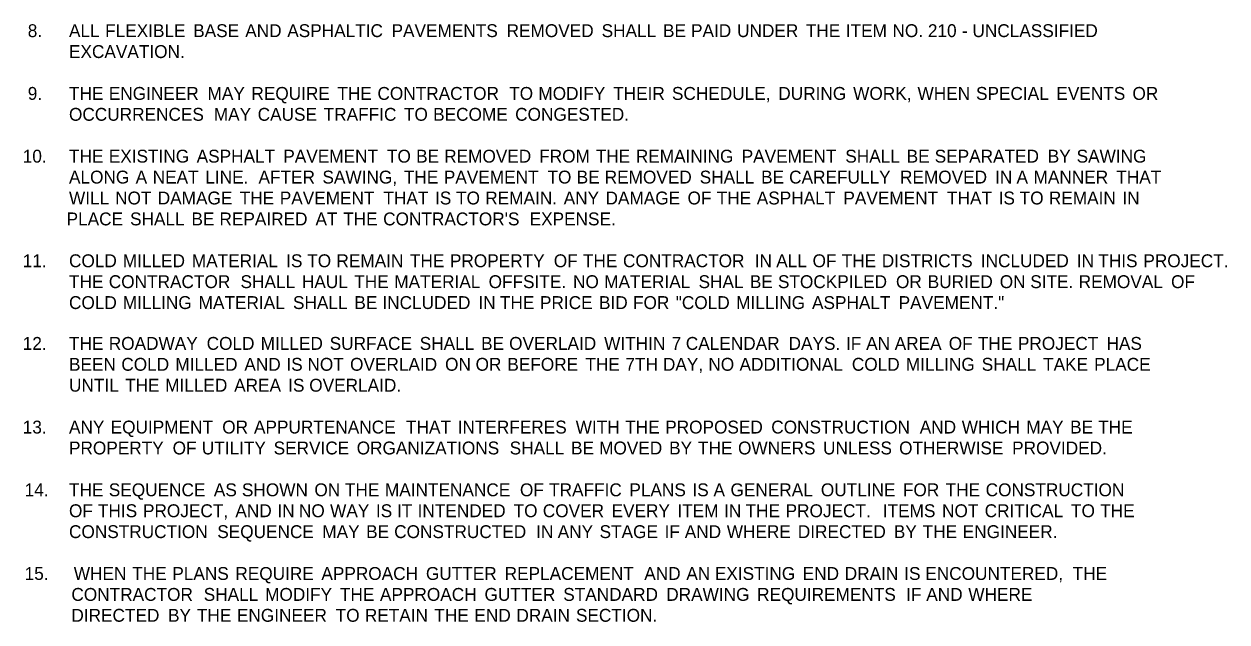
# Model space of a CAD drawing. Extents: x 1930579 to 1935779, y 596313 to 597298.
# Drawn here: x 1934273 to 1934946, y 596568 to 596902 of the extents above; entities that cross this region are included whole.
import ezdxf

# ---------------------------------------------------------------- set-up
doc = ezdxf.new("R2010")
doc.units = 0
doc.layers.add('Default', color=7, linetype='Continuous')

msp = doc.modelspace()

# ---------------------------------------------------------------- texts
at = {"layer": 'Default'}
for s, p in [('8.', (1934275.15, 596894.8)), ('ALL', (1934298.21, 596894.8)), (' FLEXIBLE', (1934315.75, 596894.8)), (' BASE', (1934364.97, 596894.8)), (' AND', (1934394.08, 596894.8)), (' ASPHALTIC', (1934417.57, 596894.8)), (' PAVEMENTS', (1934475.88, 596894.8)), (' REMOVED', (1934540.2, 596894.8)), (' SHALL', (1934593.33, 596894.8)), (' BE', (1934627.64, 596894.8)), (' PAID', (1934643.32, 596894.8)), (' UNDER', (1934669.06, 596894.8)), (' THE', (1934707.49, 596894.8)), (' ITEM', (1934729.87, 596894.8)), (' NO.', (1934755.94, 596894.8)), (' 210', (1934775.74, 596894.8)), (' -', (1934794.82, 596894.8)), (' UNCLASSIFIED', (1934800.65, 596894.8)), ('EXCAVATION.', (1934298.21, 596883.1)), ('9.', (1934275.15, 596859.7)), ('THE', (1934298.21, 596859.7)), (' ENGINEER', (1934317.79, 596859.7)), (' MAY', (1934373, 596859.7)), (' REQUIRE', (1934397.52, 596859.7)), (' THE', (1934445.62, 596859.7)), (' CONTRACTOR', (1934468, 596859.7)), (' TO', (1934541.64, 596859.7)), (' MODIFY', (1934557.95, 596859.7)), (' THEIR', (1934599.79, 596859.7)), (' SCHEDULE,', (1934632.63, 596859.7)), (' DURING', (1934692.11, 596859.7)), (' WORK,', (1934733.96, 596859.7)), (' WHEN', (1934769.95, 596859.7)), (' SPECIAL', (1934802.65, 596859.7)), (' EVENTS', (1934847.59, 596859.7)), (' OR', (1934890.11, 596859.7)), ('OCCURRENCES', (1934298.21, 596848)), (' MAY', (1934376.5, 596848)), (' CAUSE', (1934401.02, 596848)), (' TRAFFIC', (1934437.94, 596848)), (' TO', (1934482.81, 596848)), (' BECOME', (1934499.13, 596848)), (' CONGESTED.', (1934544.99, 596848)), ('10.', (1934272.35, 596824.6)), ('THE', (1934298.21, 596824.6)), (' EXISTING', (1934317.79, 596824.6)), (' ASPHALT', (1934366.92, 596824.6)), (' PAVEMENT', (1934415.36, 596824.6)), (' TO', (1934473.3, 596824.6)), (' BE', (1934489.61, 596824.6)), (' REMOVED', (1934505.29, 596824.6)), (' FROM', (1934558.42, 596824.6)), (' THE', (1934590.07, 596824.6)), (' REMAINING', (1934612.45, 596824.6)), (' PAVEMENT', (1934671.63, 596824.6)), (' SHALL', (1934729.57, 596824.6)), (' BE', (1934763.88, 596824.6)), (' SEPARATED', (1934779.55, 596824.6)), (' BY', (1934842.76, 596824.6)), (' SAWING', (1934858.9, 596824.6)), ('ALONG', (1934298.21, 596812.9)), (' A', (1934332.8, 596812.9)), (' NEAT', (1934342.32, 596812.9)), (' LINE.', (1934371.75, 596812.9)), ('  AFTER', (1934398.82, 596812.9)), (' SAWING,', (1934437.25, 596812.9)), (' THE', (1934482.74, 596812.9)), (' PAVEMENT', (1934505.12, 596812.9)), (' TO', (1934563.06, 596812.9)), (' BE', (1934579.38, 596812.9)), (' REMOVED', (1934595.05, 596812.9)), (' SHALL', (1934648.18, 596812.9)), (' BE', (1934682.49, 596812.9)), (' CAREFULLY', (1934698.17, 596812.9)), (' REMOVED', (1934760.15, 596812.9)), (' IN', (1934813.28, 596812.9)), (' A', (1934825.31, 596812.9)), (' MANNER', (1934834.83, 596812.9)), (' THAT', (1934881.08, 596812.9)), ('WILL', (1934298.21, 596801.2)), (' NOT', (1934321.32, 596801.2)), (' DAMAGE', (1934345.15, 596801.2)), (' THE', (1934391.01, 596801.2)), (' PAVEMENT', (1934413.39, 596801.2)), (' THAT', (1934471.33, 596801.2)), (' IS', (1934500.19, 596801.2)), (' TO', (1934511.96, 596801.2)), (' REMAIN.', (1934528.28, 596801.2)), (' ANY', (1934572.12, 596801.2)), (' DAMAGE', (1934595.52, 596801.2)), (' OF', (1934641.38, 596801.2)), (' THE', (1934657.69, 596801.2)), (' ASPHALT', (1934680.07, 596801.2)), (' PAVEMENT', (1934728.51, 596801.2)), (' THAT', (1934786.45, 596801.2)), (' IS', (1934815.31, 596801.2)), (' TO', (1934827.08, 596801.2)), (' REMAIN', (1934843.39, 596801.2)), (' IN', (1934884.49, 596801.2)), ('   PLACE', (1934288.85, 596789.5)), (' SHALL', (1934329.68, 596789.5)), (' BE', (1934363.99, 596789.5)), (' REPAIRED', (1934379.67, 596789.5)), (' AT', (1934433.36, 596789.5)), (' THE', (1934448.81, 596789.5)), (" CONTRACTOR'S", (1934471.19, 596789.5)), (' EXPENSE.', (1934553.08, 596789.5)), ('11.', (1934272.35, 596766.1)), ('COLD', (1934298.21, 596766.1)), (' MILLED', (1934325.62, 596766.1)), (' MATERIAL', (1934364.21, 596766.1)), (' IS', (1934416.96, 596766.1)), (' TO', (1934428.73, 596766.1)), (' REMAIN', (1934445.05, 596766.1)), (' THE', (1934486.14, 596766.1)), (' PROPERTY', (1934508.52, 596766.1)), (' OF', (1934566.59, 596766.1)), (' THE', (1934582.89, 596766.1)), (' CONTRACTOR', (1934605.27, 596766.1)), (' IN', (1934678.91, 596766.1)), (' ALL', (1934690.94, 596766.1)), (' OF', (1934711.28, 596766.1)), (' THE', (1934727.58, 596766.1)), (' DISTRICTS', (1934749.96, 596766.1)), (' INCLUDED', (1934805.33, 596766.1)), (' IN', (1934859.01, 596766.1)), (' THIS', (1934871.04, 596766.1)), (' PROJECT.', (1934896.22, 596766.1)), ('THE', (1934298.21, 596754.4)), (' CONTRACTOR', (1934317.79, 596754.4)), (' SHALL', (1934391.44, 596754.4)), (' HAUL', (1934425.75, 596754.4)), (' THE', (1934455.02, 596754.4)), (' MATERIAL', (1934477.4, 596754.4)), (' OFFSITE.', (1934530.15, 596754.4)), (' NO', (1934577.33, 596754.4)), (' MATERIAL', (1934594.77, 596754.4)), (' SHAL', (1934647.52, 596754.4)), (' BE', (1934676.24, 596754.4)), (' STOCKPILED', (1934691.91, 596754.4)), (' OR', (1934757.91, 596754.4)), (' BURIED', (1934775.65, 596754.4)), (' ON', (1934815.92, 596754.4)), (' SITE.', (1934832.98, 596754.4)), (' REMOVAL', (1934860.06, 596754.4)), (' OF', (1934911.69, 596754.4)), ('COLD', (1934298.21, 596742.7)), (' MILLING', (1934325.62, 596742.7)), (' MATERIAL', (1934368.02, 596742.7)), (' SHALL', (1934420.77, 596742.7)), (' BE', (1934455.08, 596742.7)), (' INCLUDED', (1934470.76, 596742.7)), (' IN', (1934524.44, 596742.7)), (' THE', (1934536.47, 596742.7)), (' PRICE', (1934558.85, 596742.7)), (' BID', (1934591.86, 596742.7)), (' FOR', (1934610.88, 596742.7)), (' "COLD', (1934634.78, 596742.7)), (' MILLING', (1934668.55, 596742.7)), (' ASPHALT', (1934710.96, 596742.7)), (' PAVEMENT."', (1934759.4, 596742.7)), ('12.', (1934272.35, 596719.88)), ('THE', (1934298.21, 596719.88)), (' ROADWAY', (1934317.79, 596719.88)), (' COLD', (1934372.5, 596719.88)), (' MILLED', (1934402.7, 596719.88)), (' SURFACE', (1934441.29, 596719.88)), (' SHALL', (1934491.63, 596719.88)), (' BE', (1934525.94, 596719.88)), (' OVERLAID', (1934541.61, 596719.88)), (' WITHIN', (1934594.75, 596719.88)), (' 7', (1934632.48, 596719.88)), (' CALENDAR', (1934640.41, 596719.88)), (' DAYS.', (1934697.85, 596719.88)), (' IF', (1934729.96, 596719.88)), (' AN', (1934741.23, 596719.88)), (' AREA', (1934757.18, 596719.88)), (' OF', (1934787.39, 596719.88)), (' THE', (1934803.7, 596719.88)), (' PROJECT', (1934826.08, 596719.88)), (' HAS', (1934875.62, 596719.88)), ('BEEN', (1934298.21, 596708.18)), (' COLD', (1934324.79, 596708.18)), (' MILLED', (1934354.99, 596708.18)), (' AND', (1934393.58, 596708.18)), (' IS', (1934417.08, 596708.18)), (' NOT', (1934428.85, 596708.18)), (' OVERLAID', (1934452.68, 596708.18)), (' ON', (1934505.81, 596708.18)), (' OR', (1934522.87, 596708.18)), (' BEFORE', (1934540.62, 596708.18)), (' THE', (1934584.25, 596708.18)), (' 7TH', (1934606.63, 596708.18)), (' DAY,', (1934627.61, 596708.18)), (' NO', (1934653, 596708.18)), (' ADDITIONAL', (1934670.43, 596708.18)), (' COLD', (1934733.24, 596708.18)), (' MILLING', (1934763.44, 596708.18)), (' SHALL', (1934805.85, 596708.18)), (' TAKE', (1934840.16, 596708.18)), (' PLACE', (1934868.69, 596708.18)), ('UNTIL', (1934298.21, 596696.48)), (' THE', (1934326.92, 596696.48)), (' MILLED', (1934349.29, 596696.48)), (' AREA', (1934387.88, 596696.48)), (' IS', (1934418.1, 596696.48)), (' OVERLAID.', (1934429.87, 596696.48)), ('13.', (1934272.35, 596673.08)), ('ANY', (1934298.21, 596673.08)), (' EQUIPMENT', (1934318.82, 596673.08)), (' OR', (1934381.22, 596673.08)), (' APPURTENANCE', (1934398.97, 596673.08)), (' THAT', (1934483.97, 596673.08)), (' INTERFERES', (1934512.83, 596673.08)), (' WITH', (1934578.83, 596673.08)), (' THE', (1934606.51, 596673.08)), (' PROPOSED', (1934628.89, 596673.08)), (' CONSTRUCTION', (1934688.17, 596673.08)), (' AND', (1934771.19, 596673.08)), (' WHICH', (1934794.68, 596673.08)), (' MAY', (1934830.75, 596673.08)), (' BE', (1934855.27, 596673.08)), (' THE', (1934870.95, 596673.08)), ('PROPERTY', (1934298.21, 596661.38)), (' OF', (1934353.48, 596661.38)), (' UTILITY', (1934369.79, 596661.38)), (' SERVICE', (1934409.95, 596661.38)), (' ORGANIZATIONS', (1934456.38, 596661.38)), (' SHALL', (1934541.93, 596661.38)), (' BE', (1934576.24, 596661.38)), (' MOVED', (1934591.92, 596661.38)), (' BY', (1934631.07, 596661.38)), (' THE', (1934647.21, 596661.38)), (' OWNERS', (1934669.59, 596661.38)), (' UNLESS', (1934717.13, 596661.38)), (' OTHERWISE', (1934759.66, 596661.38)), (' PROVIDED.', (1934822.84, 596661.38)), ('14.', (1934273.41, 596637.98)), ('THE', (1934298.21, 596637.98)), (' SEQUENCE', (1934317.79, 596637.98)), (' AS', (1934376.52, 596637.98)), (' SHOWN', (1934392.21, 596637.98)), (' ON', (1934432.74, 596637.98)), (' THE', (1934449.8, 596637.98)), (' MAINTENANCE', (1934472.18, 596637.98)), (' OF', (1934547.67, 596637.98)), (' TRAFFIC', (1934563.97, 596637.98)), (' PLANS', (1934608.84, 596637.98)), (' IS', (1934644.1, 596637.98)), (' A', (1934655.87, 596637.98)), (' GENERAL', (1934665.39, 596637.98)), (' OUTLINE', (1934715.91, 596637.98)), (' FOR', (1934761.77, 596637.98)), (' THE', (1934785.66, 596637.98)), (' CONSTRUCTION', (1934808.04, 596637.98)), ('OF', (1934298.21, 596626.28)), (' THIS', (1934311.72, 596626.28)), (' PROJECT,', (1934336.9, 596626.28)), (' AND', (1934388.55, 596626.28)), (' IN', (1934412.05, 596626.28)), (' NO', (1934424.08, 596626.28)), (' WAY', (1934441.52, 596626.28)), (' IS', (1934467.15, 596626.28)), (' IT', (1934478.92, 596626.28)), (' INTENDED', (1934490.45, 596626.28)), (' TO', (1934544.13, 596626.28)), (' COVER', (1934560.45, 596626.28)), (' EVERY', (1934598.89, 596626.28)), (' ITEM', (1934635.71, 596626.28)), (' IN', (1934661.78, 596626.28)), (' THE', (1934673.81, 596626.28)), (' PROJECT.', (1934696.19, 596626.28)), ('  ITEMS', (1934747.86, 596626.28)), (' NOT', (1934783.66, 596626.28)), (' CRITICAL', (1934807.49, 596626.28)), (' TO', (1934855.76, 596626.28)), (' THE', (1934872.07, 596626.28)), ('CONSTRUCTION', (1934298.21, 596614.58)), (' SEQUENCE', (1934378.43, 596614.58)), (' CONSTRUCTED', (1934477.35, 596614.58)), (' STAGE', (1934592.18, 596614.58)), (' DIRECTED', (1934703.02, 596614.58)), (' ENGINEER.', (1934795.22, 596614.58)), (' MAY', (1934437.15, 596614.58)), (' BE', (1934461.67, 596614.58)), (' IN', (1934556.74, 596614.58)), (' ANY', (1934568.77, 596614.58)), (' IF', (1934628.54, 596614.58)), (' AND', (1934639.81, 596614.58)), (' WHERE', (1934663.31, 596614.58)), (' BY', (1934756.7, 596614.58)), (' THE', (1934772.84, 596614.58)), ('15.', (1934273.41, 596591.18)), (' WHEN', (1934298.21, 596591.18)), (' THE', (1934330.92, 596591.18)), (' PLANS', (1934353.3, 596591.18)), (' REQUIRE', (1934388.55, 596591.18)), (' APPROACH', (1934436.65, 596591.18)), (' GUTTER', (1934495.1, 596591.18)), (' REPLACEMENT', (1934539.12, 596591.18)), (' AND', (1934617.18, 596591.18)), (' AN', (1934640.68, 596591.18)), (' EXISTING', (1934656.63, 596591.18)), (' END', (1934705.75, 596591.18)), (' DRAIN', (1934729.25, 596591.18)), (' IS', (1934762.52, 596591.18)), (' ENCOUNTERED,', (1934774.29, 596591.18)), (' THE', (1934856.69, 596591.18)), ('    CONTRACTOR', (1934288.85, 596579.48)), (' SHALL', (1934370.87, 596579.48)), (' MODIFY', (1934405.18, 596579.48)), (' THE', (1934447.02, 596579.48)), (' APPROACH', (1934469.4, 596579.48)), (' GUTTER', (1934527.85, 596579.48)), (' STANDARD', (1934571.87, 596579.48)), (' DRAWING', (1934629.47, 596579.48)), (' REQUIREMENTS', (1934680.25, 596579.48)), (' IF', (1934763.57, 596579.48)), (' AND', (1934774.84, 596579.48)), (' WHERE', (1934798.34, 596579.48)), ('    DIRECTED', (1934288.85, 596567.78)), (' BY', (1934350.91, 596567.78)), (' THE', (1934367.05, 596567.78)), (' ENGINEER', (1934389.43, 596567.78)), (' TO', (1934444.64, 596567.78)), (' RETAIN', (1934460.95, 596567.78)), (' THE', (1934499.82, 596567.78)), (' END', (1934522.2, 596567.78)), (' DRAIN', (1934545.69, 596567.78)), (' SECTION.', (1934578.97, 596567.78))]:
    msp.add_text(s, height=7.2, dxfattribs=at).set_placement(p)

doc.saveas('drawing.dxf')
